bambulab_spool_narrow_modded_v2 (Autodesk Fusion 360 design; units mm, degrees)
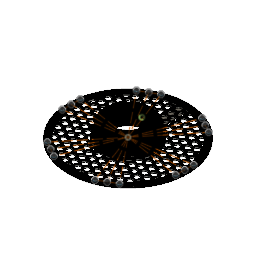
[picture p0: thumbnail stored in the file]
parameter "hole_distance_from_top" = 12.75
parameter "hole_distance_from_sides" = 32
parameter "lattice_thickness" = 3.75
parameter "lattice_diameter" = 10.25
parameter "hole_diameter" = 3.5 comment "The hole diameter around the rim"
base_mesh_feature "Base Mesh Feature"
convert_mesh "Convert Mesh"
sketch "Sketch1" plane through (0, 0, -13.45) normal (0, 0, 1) x axis (-1, 0, 0)
  line L1 (91.1991, -17.1626) -> (97.9893, -17.84)
  line L2 (90.8249, -19.0441) -> (91.1991, -17.1626)
  line L3 (97.9893, -17.84) -> (90.8249, -19.0441)
  line L4 (94.8205, 15.0016) -> (94.8184, -14.9969)
  line L5 (34.4185, 89.6178) -> (60.3969, 74.6167)
  line L6 (-60.402, 74.6162) -> (-34.4215, 89.6136)
  line L7 (-94.8205, -15.0016) -> (-94.8184, 14.9969)
  line L8 (-34.4185, -89.6178) -> (-60.3969, -74.6167)
  line L9 (60.402, -74.6162) -> (34.4215, -89.6136)
  line L10 (0, 0) -> (47.4118, -82.1149)
  line L11 (-47.4077, -82.1173) -> (0, 0)
  line L12 (-94.8195, -0.0023) -> (0, 0)
  line L13 (-47.4118, 82.1149) -> (0, 0)
  line L14 (47.4077, 82.1173) -> (0, 0)
  line L15 (94.8195, 0.0023) -> (0, 0)
  line L16 (0, 0) -> (60.3969, 74.6167)
  line L17 (34.4185, 89.6178) -> (0, 0)
  line L18 (-34.4215, 89.6136) -> (0, 0)
  line L19 (-60.402, 74.6162) -> (0, 0)
  line L20 (-94.8184, 14.9969) -> (0, 0)
  line L21 (-94.8205, -15.0016) -> (0, 0)
  line L22 (-34.4185, -89.6178) -> (0, 0)
  line L23 (-60.3969, -74.6167) -> (0, 0)
  line L24 (34.4215, -89.6136) -> (0, 0)
  line L25 (60.402, -74.6162) -> (0, 0)
  line L26 (94.8184, -14.9969) -> (0, 0)
  line L27 (94.8205, 15.0016) -> (0, 0)
  circle C1 centre (94.8184, -14.9969) radius 2
  circle C2 centre (94.8205, 15.0016) radius 2
  circle C3 centre (60.3969, 74.6167) radius 2
  circle C4 centre (-34.4215, 89.6136) radius 2
  circle C5 centre (-94.8184, 14.9969) radius 2
  circle C6 centre (-60.3969, -74.6167) radius 2
  circle C7 centre (34.4215, -89.6136) radius 2
  circle C8 centre (34.4185, 89.6178) radius 2
  circle C9 centre (-60.402, 74.6162) radius 2
  circle C10 centre (-94.8205, -15.0016) radius 2
  circle C11 centre (-34.4185, -89.6178) radius 2
  circle C12 centre (60.402, -74.6162) radius 2
  point P1 (0, 0)
  point P7 (0, 0)
  point P5 (94.8184, -14.9969)
  point P18 (94.8184, -14.9969)
  point P6 (94.8205, 15.0016)
  point P19 (94.8205, 15.0016)
  point P8 (60.3969, 74.6167)
  point P20 (60.3969, 74.6167)
  point P13 (34.4185, 89.6178)
  point P21 (34.4185, 89.6178)
  point P9 (-34.4215, 89.6136)
  point P22 (-34.4215, 89.6136)
  point P14 (-60.402, 74.6162)
  point P23 (-60.402, 74.6162)
  point P10 (-94.8184, 14.9969)
  point P24 (-94.8184, 14.9969)
  point P15 (-94.8205, -15.0016)
  point P25 (-94.8205, -15.0016)
  point P11 (-60.3969, -74.6167)
  point P26 (-60.3969, -74.6167)
  point P16 (-34.4185, -89.6178)
  point P27 (-34.4185, -89.6178)
  point P12 (34.4215, -89.6136)
  point P28 (34.4215, -89.6136)
  point P17 (60.402, -74.6162)
  point P29 (60.402, -74.6162)
  point P30 (47.4118, -82.1149)
  point P31 (94.8195, 0.0023)
  point P32 (-47.4077, -82.1173)
  point P33 (-94.8195, -0.0023)
  point P34 (-47.4118, 82.1149)
  point P35 (47.4077, 82.1173)
  point P36 (47.4118, -82.1149)
  point P37 (0, 0)
  point P38 (-47.4077, -82.1173)
  point P39 (0, 0)
  point P40 (-94.8195, -0.0023)
  point P41 (0, 0)
  point P42 (-47.4118, 82.1149)
  point P43 (0, 0)
  point P44 (47.4077, 82.1173)
  point P45 (0, 0)
  point P46 (94.8195, 0.0023)
  point P47 (0, 0)
  point P48 (34.4185, 89.6178)
  point P49 (0, 0)
  point P50 (-34.4215, 89.6136)
  point P51 (0, 0)
  point P52 (-94.8184, 14.9969)
  point P53 (0, 0)
  point P54 (-94.8205, -15.0016)
  point P55 (-34.4185, -89.6178)
  point P56 (-60.3969, -74.6167)
  point P57 (0, 0)
  point P58 (60.402, -74.6162)
  point P59 (0, 0)
  point P60 (94.8184, -14.9969)
  point P61 (0, 0)
  point P62 (94.8205, 15.0016)
  coincident P1 P7
  coincident P5 P18
  coincident P6 P19
  coincident P8 P20
  coincident P13 P21
  coincident P9 P22
  coincident P14 P23
  coincident P10 P24
  coincident P15 P25
  coincident P11 P26
  coincident P16 P27
  coincident P12 P28
  coincident P17 P29
  midpoint L9 P30
  midpoint L4 P31
  midpoint L8 P32
  midpoint L7 P33
  midpoint L6 P34
  midpoint L5 P35
  coincident P30 P36
  coincident P1 P37
  coincident P32 P38
  coincident P1 P39
  coincident P33 P40
  coincident P7 P41
  coincident P34 P42
  coincident P7 P43
  coincident P35 P44
  coincident P1 P45
  coincident P31 P46
  coincident P7 P47
  coincident P13 P48
  coincident P7 P49
  coincident P9 P50
  coincident P7 P51
  coincident P10 P52
  coincident P7 P53
  coincident P15 P54
  coincident P16 P55
  coincident P11 P56
  coincident P1 P57
  coincident P17 P58
  coincident P1 P59
  coincident P5 P60
  coincident P7 P61
  coincident P6 P62
  dimension "d1" diameter C2 = 4
  dimension "d2" diameter C1 = 4
  dimension "d4" C-Pattern1-Angle = 360
  dimension "d6" C-Pattern2-Angle = 360
extrude "Extrude1" cut sketch "Sketch1" profile of C3 C4 C6 C7 C8 C9 C11 C12 against normal blind 11
sketch "Sketch2" plane through (0, 0, 0) normal (1, 0, 0) x axis (0, 1, 0)
  line L1 (0, -25) -> (0, 24)
  line L2 (-63, 0) -> (50, 0)
  circle C1 centre (-32, -12.75) radius 1.1
  circle C2 centre (32, -12.75) radius 1.1
  point P2 (-32, -12.75)
  point P3 (32, -12.75)
  vertical L1
  horizontal L2
  dimension "d9" diameter C2 = 2.2
  dimension "d10" diameter C1 = 2.2
  dimension "d11" distance P2 L1 = 32 (= "hole_distance_from_sides")
  dimension "d12" distance P3 L1 = 32 (= "hole_distance_from_sides")
  dimension "d13" distance P3 L2 = 12.75 (= "hole_distance_from_top")
  dimension "d16" distance P2 L2 = 12.75 (= "hole_distance_from_top")
work_plane "WorkPlane1" AlongDistance -61
work_plane "WorkPlane2" AlongDistance -64
work_plane "WorkPlane3" AlongDistance 64
work_plane "WorkPlane4" AlongDistance 65
sketch "Sketch3" plane through (64, 0, 0) normal (1, 0, 0) x axis (0, 1, 0)
  circle C1 centre (-32, -12.75) radius 1.1
  circle C2 centre (32, -12.75) radius 1.1
extrude "Extrude2" cut sketch "Sketch3" against normal blind 57
sketch "Sketch4" plane through (-61, 0, 0) normal (1, 0, 0) x axis (0, 1, 0)
  circle C1 centre (32, -12.75) radius 1.1
  circle C2 centre (-32, -12.75) radius 1.1
extrude "Extrude3" cut sketch "Sketch4" along normal blind 56
sketch "Sketch5" plane through (0, 65, 0) normal (0, 1, 0) x axis (1, 0, 0)
  line L1 (0, 26) -> (0, -23)
  line L2 (-49.4611, 0) -> (56, 0)
  circle C1 centre (32, 12.75) radius 1.1
  circle C2 centre (-32, 12.75) radius 1.1
  point P7 (-32, 12.75)
  point P6 (32, 12.75)
  vertical L1
  horizontal L2
  dimension "d25" diameter C1 = 2.2
  dimension "d26" diameter C2 = 2.2
  dimension "d27" distance L2 P7 = 12.75 (= "hole_distance_from_top")
  dimension "d28" distance L2 P6 = 12.75 (= "hole_distance_from_top")
  dimension "d29" distance L1 P6 = 32 (= "hole_distance_from_sides")
  dimension "d30" distance L1 P7 = 32 (= "hole_distance_from_sides")
extrude "Extrude4" cut sketch "Sketch5" profile of C1 C2 against normal blind 60
sketch "Sketch6" plane through (0, -64, 0) normal (0, 1, 0) x axis (1, 0, 0)
  circle C1 centre (32, 12.75) radius 1.1
  circle C2 centre (-32, 12.75) radius 1.1
extrude "Extrude5" cut sketch "Sketch6" along normal blind 60
sketch "Label" plane through (0, 0, -17.05) normal (0, 0, -1) x axis (1, 0, 0)
  line L1 (-1.2532, -46.0788) -> (-0.6281, -46.0197)
  line L2 (-1.8735, -46.1771) -> (-1.2532, -46.0788)
  line L3 (-2.4873, -46.3143) -> (-1.8735, -46.1771)
  line L4 (-3.0901, -46.4894) -> (-2.4873, -46.3143)
  line L5 (-3.6808, -46.7021) -> (-3.0901, -46.4894)
  line L6 (-0.6281, -46.0197) -> (0, -46.0001)
  line L7 (0.6281, -46.0197) -> (0, -46.0001)
  line L8 (1.2532, -46.0788) -> (0.6281, -46.0197)
  line L9 (1.8735, -46.1771) -> (1.2532, -46.0788)
  line L10 (2.4872, -46.3143) -> (1.8735, -46.1771)
  line L11 (3.0901, -46.4894) -> (2.4872, -46.3143)
  line L12 (3.6808, -46.7021) -> (3.0901, -46.4894)
  line L13 (4.2582, -46.9519) -> (3.6808, -46.7021)
  line L14 (4.8175, -47.2369) -> (4.2582, -46.9519)
  line L15 (5.3579, -47.5565) -> (4.8175, -47.2369)
  line L16 (5.878, -47.91) -> (5.3579, -47.5565)
  line L17 (6.3742, -48.2949) -> (5.878, -47.91)
  line L18 (6.8453, -48.7102) -> (6.3742, -48.2949)
  line L19 (7.2897, -49.1546) -> (6.8453, -48.7102)
  line L20 (7.7051, -49.6258) -> (7.2897, -49.1546)
  line L21 (8.0901, -50.1221) -> (7.7051, -49.6258)
  line L22 (8.4431, -50.6416) -> (8.0901, -50.1221)
  line L23 (8.7631, -51.1825) -> (8.4431, -50.6416)
  line L24 (9.0483, -51.7422) -> (8.7631, -51.1825)
  line L25 (9.2976, -52.3185) -> (9.0483, -51.7422)
  line L26 (9.5106, -52.91) -> (9.2976, -52.3185)
  line L27 (9.6858, -53.5131) -> (9.5106, -52.91)
  line L28 (9.8228, -54.1259) -> (9.6858, -53.5131)
  line L29 (9.9212, -54.7468) -> (9.8228, -54.1259)
  line L30 (9.9802, -55.3716) -> (9.9212, -54.7468)
  line L31 (10, -56) -> (9.9802, -55.3716)
  line L32 (10, -82) -> (10, -56)
  line L33 (-9.2976, -52.3185) -> (-9.0483, -51.7422)
  line L34 (-9.0483, -51.7422) -> (-8.7631, -51.1825)
  line L35 (-8.7631, -51.1825) -> (-8.4431, -50.6416)
  line L36 (-8.4431, -50.6416) -> (-8.0901, -50.1221)
  line L37 (-8.0901, -50.1221) -> (-7.7051, -49.6258)
  line L38 (-7.7051, -49.6258) -> (-7.2897, -49.1546)
  line L39 (-7.2897, -49.1546) -> (-6.8453, -48.7102)
  line L40 (-6.8453, -48.7102) -> (-6.3742, -48.2949)
  line L41 (-6.3742, -48.2949) -> (-5.878, -47.91)
  line L42 (-5.878, -47.91) -> (-5.3579, -47.5565)
  line L43 (-5.3579, -47.5565) -> (-4.8175, -47.2369)
  line L44 (-4.8175, -47.2369) -> (-4.2582, -46.9519)
  line L45 (-4.2582, -46.9519) -> (-3.6808, -46.7021)
  line L46 (-9.5106, -52.91) -> (-9.2976, -52.3185)
  line L47 (-9.6858, -53.5131) -> (-9.5106, -52.91)
  line L48 (-9.8228, -54.1259) -> (-9.6858, -53.5131)
  line L49 (-9.9212, -54.7468) -> (-9.8228, -54.1259)
  line L50 (-9.9802, -55.3716) -> (-9.9212, -54.7468)
  line L51 (-10, -56) -> (-9.9802, -55.3716)
  line L52 (-10, -82) -> (-10, -56)
  line L53 (9.9802, -82.6284) -> (10, -82)
  line L54 (9.9212, -83.2532) -> (9.9802, -82.6284)
  line L55 (9.8228, -83.8741) -> (9.9212, -83.2532)
  line L56 (9.6858, -84.4869) -> (9.8228, -83.8741)
  line L57 (9.5106, -85.09) -> (9.6858, -84.4869)
  line L58 (9.2976, -85.6815) -> (9.5106, -85.09)
  line L59 (9.0483, -86.2578) -> (9.2976, -85.6815)
  line L60 (8.7631, -86.8175) -> (9.0483, -86.2578)
  line L61 (8.4431, -87.3584) -> (8.7631, -86.8175)
  line L62 (8.0901, -87.8779) -> (8.4431, -87.3584)
  line L63 (7.7051, -88.3742) -> (8.0901, -87.8779)
  line L64 (7.2897, -88.8454) -> (7.7051, -88.3742)
  line L65 (6.8453, -89.2898) -> (7.2897, -88.8454)
  line L66 (6.3742, -89.7051) -> (6.8453, -89.2898)
  line L67 (5.878, -90.09) -> (6.3742, -89.7051)
  line L68 (5.3579, -90.4435) -> (5.878, -90.09)
  line L69 (4.8175, -90.7631) -> (5.3579, -90.4435)
  line L70 (4.2582, -91.0481) -> (4.8175, -90.7631)
  line L71 (3.6808, -91.2979) -> (4.2582, -91.0481)
  line L72 (3.0901, -91.5106) -> (3.6808, -91.2979)
  line L73 (2.4872, -91.6857) -> (3.0901, -91.5106)
  line L74 (1.8735, -91.8229) -> (2.4872, -91.6857)
  line L75 (1.2532, -91.9212) -> (1.8735, -91.8229)
  line L76 (0.6281, -91.9803) -> (1.2532, -91.9212)
  line L77 (0, -92) -> (0.6281, -91.9803)
  line L78 (0, -92) -> (-0.6281, -91.9803)
  line L79 (-0.6281, -91.9803) -> (-1.2532, -91.9212)
  line L80 (-1.2532, -91.9212) -> (-1.8735, -91.8229)
  line L81 (-1.8735, -91.8229) -> (-2.4873, -91.6857)
  line L82 (-2.4873, -91.6857) -> (-3.0901, -91.5106)
  line L83 (-3.0901, -91.5106) -> (-3.6808, -91.2979)
  line L84 (-3.6808, -91.2979) -> (-4.2582, -91.0481)
  line L85 (-4.2582, -91.0481) -> (-4.8175, -90.7631)
  line L86 (-4.8175, -90.7631) -> (-5.3579, -90.4435)
  line L87 (-5.3579, -90.4435) -> (-5.878, -90.09)
  line L88 (-5.878, -90.09) -> (-6.3742, -89.7051)
  line L89 (-6.3742, -89.7051) -> (-6.8453, -89.2898)
  line L90 (-6.8453, -89.2898) -> (-7.2897, -88.8454)
  line L91 (-7.2897, -88.8454) -> (-7.7051, -88.3742)
  line L92 (-7.7051, -88.3742) -> (-8.0901, -87.8779)
  line L93 (-8.0901, -87.8779) -> (-8.4431, -87.3584)
  line L94 (-8.4431, -87.3584) -> (-8.7631, -86.8175)
  line L95 (-8.7631, -86.8175) -> (-9.0483, -86.2578)
  line L96 (-9.0483, -86.2578) -> (-9.2976, -85.6815)
  line L97 (-9.2976, -85.6815) -> (-9.5106, -85.09)
  line L98 (-9.5106, -85.09) -> (-9.6858, -84.4869)
  line L99 (-9.6858, -84.4869) -> (-9.8228, -83.8741)
  line L100 (-9.8228, -83.8741) -> (-9.9212, -83.2532)
  line L101 (-9.9212, -83.2532) -> (-9.9802, -82.6284)
  line L102 (-9.9802, -82.6284) -> (-10, -82)
  line L103 (-10.3182, -83.3033) -> (-10.3796, -82.6536)
  line L104 (-10.2159, -83.9491) -> (-10.3182, -83.3033)
  line L105 (-10.0734, -84.5864) -> (-10.2159, -83.9491)
  line L106 (-9.8912, -85.2136) -> (-10.0734, -84.5864)
  line L107 (-9.6697, -85.8289) -> (-9.8912, -85.2136)
  line L108 (-9.4104, -86.4282) -> (-9.6697, -85.8289)
  line L109 (-9.1138, -87.0103) -> (-9.4104, -86.4282)
  line L110 (-8.781, -87.5728) -> (-9.1138, -87.0103)
  line L111 (-8.4139, -88.1131) -> (-8.781, -87.5728)
  line L112 (-8.0135, -88.6293) -> (-8.4139, -88.1131)
  line L113 (-7.5814, -89.1194) -> (-8.0135, -88.6293)
  line L114 (-7.1193, -89.5816) -> (-7.5814, -89.1194)
  line L115 (-6.6293, -90.0135) -> (-7.1193, -89.5816)
  line L116 (-6.1133, -90.4137) -> (-6.6293, -90.0135)
  line L117 (-5.5723, -90.7814) -> (-6.1133, -90.4137)
  line L118 (-5.0103, -91.1138) -> (-5.5723, -90.7814)
  line L119 (-4.4285, -91.4102) -> (-5.0103, -91.1138)
  line L120 (-3.8281, -91.67) -> (-4.4285, -91.4102)
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  dimension "d59" = 0.4
sketch "Sketch7" plane through (0, 0, -14.55) normal (0, 0, 1) x axis (-1, 0, 0)
  line L1 (-2.5625, -4.4384) -> (-5.125, 0)
  line L2 (-5.125, 0) -> (-2.5625, 4.4384)
  line L3 (8.3726, -10.7518) -> (5.8101, -6.3134)
  line L4 (16.0601, -6.3134) -> (13.4976, -10.7518)
  line L5 (13.4976, -10.7518) -> (8.3726, -10.7518)
  line L6 (2.5625, -8.1884) -> (5.125, -12.6268)
  line L7 (5.125, -12.6268) -> (2.5625, -17.0651)
  line L8 (16.0601, -17.0651) -> (16.0601, 10.7518)
  line L9 (2.5625, -17.0651) -> (-2.5625, -17.0651)
  line L10 (5.125, 0) -> (2.5625, -4.4384)
  line L11 (-2.5625, 4.4384) -> (2.5625, 4.4384)
  line L12 (-5.125, -17.0651) -> (16.0601, -17.0651)
  line L13 (-5.125, 10.7518) -> (16.0601, 10.7518)
  line L14 (-37, 0) -> (37, 0)
  line L15 (2.5625, -4.4384) -> (-2.5625, -4.4384)
  line L16 (-2.5625, -17.0651) -> (-5.125, -12.6268)
  line L17 (2.5625, 4.4384) -> (5.125, 0)
  line L18 (13.4976, 10.7518) -> (16.0601, 6.3134)
  line L19 (5.8101, 6.3134) -> (8.3726, 10.7518)
  line L20 (16.0601, 6.3134) -> (13.4976, 1.875)
  line L21 (13.4976, 1.875) -> (8.3726, 1.875)
  line L22 (-2.5625, -8.1884) -> (2.5625, -8.1884)
  line L23 (8.3726, 10.7518) -> (13.4976, 10.7518)
  line L24 (8.3726, -1.875) -> (13.4976, -1.875)
  line L25 (8.3726, 1.875) -> (5.8101, 6.3134)
  line L26 (5.8101, -6.3134) -> (8.3726, -1.875)
  line L27 (13.4976, -1.875) -> (16.0601, -6.3134)
  line L28 (-5.125, -17.0651) -> (-5.125, 10.7518)
  line L29 (0, -45.5) -> (0, 45.5)
  line L30 (-5.125, -12.6268) -> (-2.5625, -8.1884)
  line L31 (-100.8005, -108.8944) -> (-103.363, -113.3327)
  line L32 (-103.363, -113.3327) -> (-108.488, -113.3327)
  line L33 (-108.488, -113.3327) -> (-111.0505, -108.8944)
  line L34 (-111.0505, -108.8944) -> (-108.488, -104.456)
  line L35 (-108.488, -104.456) -> (-103.363, -104.456)
  line L36 (-103.363, -104.456) -> (-100.8005, -108.8944)
  line L37 (-97.5529, -107.0194) -> (-100.1154, -102.581)
  line L38 (-92.4279, -107.0194) -> (-97.5529, -107.0194)
  line L39 (-89.8654, -102.581) -> (-92.4279, -107.0194)
  line L40 (-92.4279, -98.1426) -> (-89.8654, -102.581)
  line L41 (-97.5529, -98.1426) -> (-92.4279, -98.1426)
  line L42 (-100.1154, -102.581) -> (-97.5529, -98.1426)
  line L43 (-100.8005, -96.2676) -> (-103.363, -100.706)
  line L44 (-103.363, -100.706) -> (-108.488, -100.706)
  line L45 (-108.488, -100.706) -> (-111.0505, -96.2676)
  line L46 (-111.0505, -96.2676) -> (-108.488, -91.8292)
  line L47 (-108.488, -91.8292) -> (-103.363, -91.8292)
  line L48 (-103.363, -91.8292) -> (-100.8005, -96.2676)
  line L49 (-97.5529, -94.3926) -> (-100.1154, -89.9542)
  line L50 (-92.4279, -94.3926) -> (-97.5529, -94.3926)
  line L51 (-89.8654, -89.9542) -> (-92.4279, -94.3926)
  line L52 (-92.4279, -85.5158) -> (-89.8654, -89.9542)
  line L53 (-100.1154, -89.9542) -> (-97.5529, -85.5158)
  line L54 (-97.5529, -85.5158) -> (-92.4279, -85.5158)
  line L55 (-79.6154, -108.8944) -> (-82.1779, -113.3327)
  line L56 (-82.1779, -113.3327) -> (-87.3029, -113.3327)
  line L57 (-87.3029, -113.3327) -> (-89.8654, -108.8944)
  line L58 (-89.8654, -108.8944) -> (-87.3029, -104.456)
  line L59 (-87.3029, -104.456) -> (-82.1779, -104.456)
  line L60 (-82.1779, -104.456) -> (-79.6154, -108.8944)
  line L61 (-76.3678, -107.0194) -> (-78.9303, -102.581)
  line L62 (-71.2428, -107.0194) -> (-76.3678, -107.0194)
  line L63 (-68.6803, -102.581) -> (-71.2428, -107.0194)
  line L64 (-71.2428, -98.1426) -> (-68.6803, -102.581)
  line L65 (-76.3678, -98.1426) -> (-71.2428, -98.1426)
  line L66 (-78.9303, -102.581) -> (-76.3678, -98.1426)
  line L67 (-79.6154, -96.2676) -> (-82.1779, -100.706)
  line L68 (-82.1779, -100.706) -> (-87.3029, -100.706)
  line L69 (-87.3029, -100.706) -> (-89.8654, -96.2676)
  line L70 (-89.8654, -96.2676) -> (-87.3029, -91.8292)
  line L71 (-87.3029, -91.8292) -> (-82.1779, -91.8292)
  line L72 (-82.1779, -91.8292) -> (-79.6154, -96.2676)
  line L73 (-76.3678, -94.3926) -> (-78.9303, -89.9542)
  line L74 (-71.2428, -94.3926) -> (-76.3678, -94.3926)
  line L75 (-68.6803, -89.9542) -> (-71.2428, -94.3926)
  line L76 (-71.2428, -85.5158) -> (-68.6803, -89.9542)
  line L77 (-78.9303, -89.9542) -> (-76.3678, -85.5158)
  line L78 (-76.3678, -85.5158) -> (-71.2428, -85.5158)
  line L79 (-58.4303, -108.8944) -> (-60.9928, -113.3327)
  line L80 (-60.9928, -113.3327) -> (-66.1178, -113.3327)
  line L81 (-66.1178, -113.3327) -> (-68.6803, -108.8944)
  line L82 (-68.6803, -108.8944) -> (-66.1178, -104.456)
  line L83 (-66.1178, -104.456) -> (-60.9928, -104.456)
  line L84 (-60.9928, -104.456) -> (-58.4303, -108.8944)
  line L85 (-55.1827, -107.0194) -> (-57.7452, -102.581)
  line L86 (-50.0577, -107.0194) -> (-55.1827, -107.0194)
  line L87 (-47.4952, -102.581) -> (-50.0577, -107.0194)
  line L88 (-50.0577, -98.1426) -> (-47.4952, -102.581)
  line L89 (-55.1827, -98.1426) -> (-50.0577, -98.1426)
  line L90 (-57.7452, -102.581) -> (-55.1827, -98.1426)
  line L91 (-58.4303, -96.2676) -> (-60.9928, -100.706)
  line L92 (-60.9928, -100.706) -> (-66.1178, -100.706)
  line L93 (-66.1178, -100.706) -> (-68.6803, -96.2676)
  line L94 (-68.6803, -96.2676) -> (-66.1178, -91.8292)
  line L95 (-66.1178, -91.8292) -> (-60.9928, -91.8292)
  line L96 (-60.9928, -91.8292) -> (-58.4303, -96.2676)
  line L97 (-55.1827, -94.3926) -> (-57.7452, -89.9542)
  line L98 (-50.0577, -94.3926) -> (-55.1827, -94.3926)
  line L99 (-47.4952, -89.9542) -> (-50.0577, -94.3926)
  line L100 (-50.0577, -85.5158) -> (-47.4952, -89.9542)
  line L101 (-57.7452, -89.9542) -> (-55.1827, -85.5158)
  line L102 (-55.1827, -85.5158) -> (-50.0577, -85.5158)
  line L103 (-37.2452, -108.8944) -> (-39.8077, -113.3327)
  line L104 (-39.8077, -113.3327) -> (-44.9327, -113.3327)
  line L105 (-44.9327, -113.3327) -> (-47.4952, -108.8944)
  line L106 (-47.4952, -108.8944) -> (-44.9327, -104.456)
  line L107 (-44.9327, -104.456) -> (-39.8077, -104.456)
  line L108 (-39.8077, -104.456) -> (-37.2452, -108.8944)
  line L109 (-33.9976, -107.0194) -> (-36.5601, -102.581)
  line L110 (-28.8726, -107.0194) -> (-33.9976, -107.0194)
  line L111 (-26.3101, -102.581) -> (-28.8726, -107.0194)
  line L112 (-28.8726, -98.1426) -> (-26.3101, -102.581)
  line L113 (-33.9976, -98.1426) -> (-28.8726, -98.1426)
  line L114 (-36.5601, -102.581) -> (-33.9976, -98.1426)
  line L115 (-37.2452, -96.2676) -> (-39.8077, -100.706)
  line L116 (-39.8077, -100.706) -> (-44.9327, -100.706)
  line L117 (-44.9327, -100.706) -> (-47.4952, -96.2676)
  line L118 (-47.4952, -96.2676) -> (-44.9327, -91.8292)
  line L119 (-44.9327, -91.8292) -> (-39.8077, -91.8292)
  line L120 (-39.8077, -91.8292) -> (-37.2452, -96.2676)
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  point P1 (0, 0)
  point P2 (0, 0)
  point P3 (0, 0)
  point P4 (0, 0)
  point P5 (0, 0)
  point P41 (0, 0)
  point P6 (0, 0)
  point P7 (0, 0)
  point P14 (0, 0)
  point P21 (0, -12.6268)
  point P10 (-5.125, 0)
  point P27 (16.0601, -6.3134)
  point P43 (16.0601, -17.0651)
  point P44 (-5.125, -17.0651)
  point P40 (-5.125, 10.7518)
  point P42 (16.0601, 10.7518)
  point P2661 (0, 0)
  point P13 (5.125, 0)
  point P8 (2.5625, 4.4384)
  point P11 (-2.5625, -4.4384)
  point P16 (5.125, -12.6268)
  point P19 (-5.125, -12.6268)
  point P15 (2.5625, -17.0651)
  point P18 (-2.5625, -8.1884)
  point P30 (5.8101, -6.3134)
  point P33 (16.0601, 6.3134)
  point P36 (5.8101, 6.3134)
  coincident P1 P2
  coincident P2 P3
  coincident P1 P4
  coincident P5 P41
  coincident P6 P41
  coincident P7 P41
  coincident P6 P14
  vertical L29
  horizontal L14
  coincident P41 L29
  midpoint P5 L14
  midpoint P41 L29
  coincident P21 L29
  parallel L14 L15
  parallel L5 L14
  parallel L14 L21
  vertical L28
  vertical L8
  coincident P10 L28
  coincident P27 L8
  perpendicular L8 L13
  horizontal L12
  collinear L13 L23
  collinear L9 L12
  coincident P43 L8
  coincident P44 L28
  coincident P40 L13
  coincident P42 L8
  coincident P2 P2661
  dimension "d35" diameter = 183.4
  dimension "d38" diameter = 179.65 (= "183.4 mm - lattice_thickness")
  dimension "d63" distance P10 P13 = 10.25 (= "lattice_diameter")
  dimension "d64" distance P8 P11 = 10.25 (= "lattice_diameter")
  dimension "d65" distance P16 P19 = 10.25 (= "lattice_diameter")
  dimension "d66" distance P15 P18 = 10.25 (= "lattice_diameter")
  dimension "d67" distance L15 L22 = 3.75 (= "lattice_thickness")
  dimension "d68" distance P27 P30 = 10.25 (= "lattice_diameter")
  dimension "d69" distance L10 L26 = 3.75 (= "lattice_thickness")
  dimension "d70" distance L3 L6 = 3.75 (= "lattice_thickness")
  dimension "d71" distance P33 P36 = 10.25 (= "lattice_diameter")
  dimension "d72" distance L21 L24 = 3.75 (= "lattice_thickness")
  dimension "d73" distance L17 L25 = 3.75 (= "lattice_thickness")
  dimension "d74" distance P43 P44 = 21.1851
  dimension "d75" distance P42 P43 = 27.8169
  dimension "d56" diameter = 89
  dimension "d54" R-Pattern1-uDistance = 21.1851
  dimension "d55" R-Pattern1-vDistance = 24.0669 (= "27.816899 mm - lattice_thickness")
extrude "Extrude6" cut sketch "Sketch7" distance 30
extrude "Extrude7" add sketch "Label" profile of L1 L2 L3 L4 L5 L6 L7 L8 L9 L10 L11 L12 L13 L14 L15 L16 L17 L18 L19 L20 L21 L22 L23 L24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 against normal blind 0.4
sketch "Sketch13" plane through (-3.8901, 27.2222, 0) normal (0.1415, -0.9899, 0) x axis (0.9899, 0.1415, 0)
  line L1 (3.3587, 0) -> (-3.6413, 0)
  line L2 (-0.1413, 3.5) -> (-3.6413, 0)
  line L3 (3.3587, 0) -> (-0.1413, 3.5)
  line L4 (-0.1413, 0) -> (-0.1413, 3.5)
  point P2 (-0.1413, 0)
  point P6 (-0.1413, 0)
  point P5 (-0.1413, 3.5)
  horizontal L1
  coincident P2 P6
  coincident P2 L1
  equal L2 L3
  perpendicular L1 L4
  dimension "d92" distance P5 P6 = 3.5
  dimension "d93" angle L2 L3 = 90
sketch "Sketch15" plane through (3.8901, -27.2222, 0) normal (-0.1415, 0.9899, 0) x axis (-0.9899, -0.1415, 0)
  line L1 (-0.1438, 3.5) -> (3.3562, 0)
  line L2 (-3.6438, 0) -> (-0.1438, 3.5)
  line L3 (-3.6438, 0) -> (3.3562, 0)
extrude "Extrude10" cut sketch "Sketch13" profile of L1 L2 L3 along normal blind 5 and against normal blind 0.5
chamfer "Chamfer1" distance 0.5 Rotate Angle 45
extrude "Extrude11" cut sketch "Sketch15" along normal blind 5 and against normal blind 0.5
chamfer "Chamfer2" distance 0.5 Rotate Angle 45
extrude "Extrude12" add sketch "Sketch1" profile of C1 C2 C3 C4 C5 C6 C7 C8 C9 C10 C11 C12 against normal blind 3.6
work_plane "WorkPlane5" RotateAngle 45
sketch "Sketch16" plane through (17.2108, -44.8068, -13.45) normal (-0.6601, -0.2535, 0.7071) x axis (0.3586, -0.9335, 0)
  circle C1 centre (48, 0) radius 1.75
  dimension "d110" diameter C1 = 3.5 (= "hole_diameter")
extrude "Extrude13" new body sketch "Sketch16" distance 20
work_plane "WorkPlane6" RotateAngle -45
sketch "Sketch17" plane through (30.201, -37.3081, -13.45) normal (0.5496, 0.4449, 0.7071) x axis (0.6292, -0.7773, 0)
  circle C1 centre (48, 0) radius 1.75
  dimension "d114" diameter C1 = 3.5 (= "hole_diameter")
extrude "Extrude14" new body sketch "Sketch17" distance 20
circular_pattern "C-Pattern1" TotalAngle 360
combine "Combine1"
named bodies: "bambulab_spool_narrow"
